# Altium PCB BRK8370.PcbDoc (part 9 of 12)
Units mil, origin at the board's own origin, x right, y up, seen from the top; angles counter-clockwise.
Board outline 8267.72 x 5708.66 mil, 6 copper layers (L1-TOP, L2-GND, L3-PWR, L4-PWR, L5-GND, L6-BOT), stack 68.606 mil thick; 319 components, 516 nets, 2008 pads, 1743 vias.
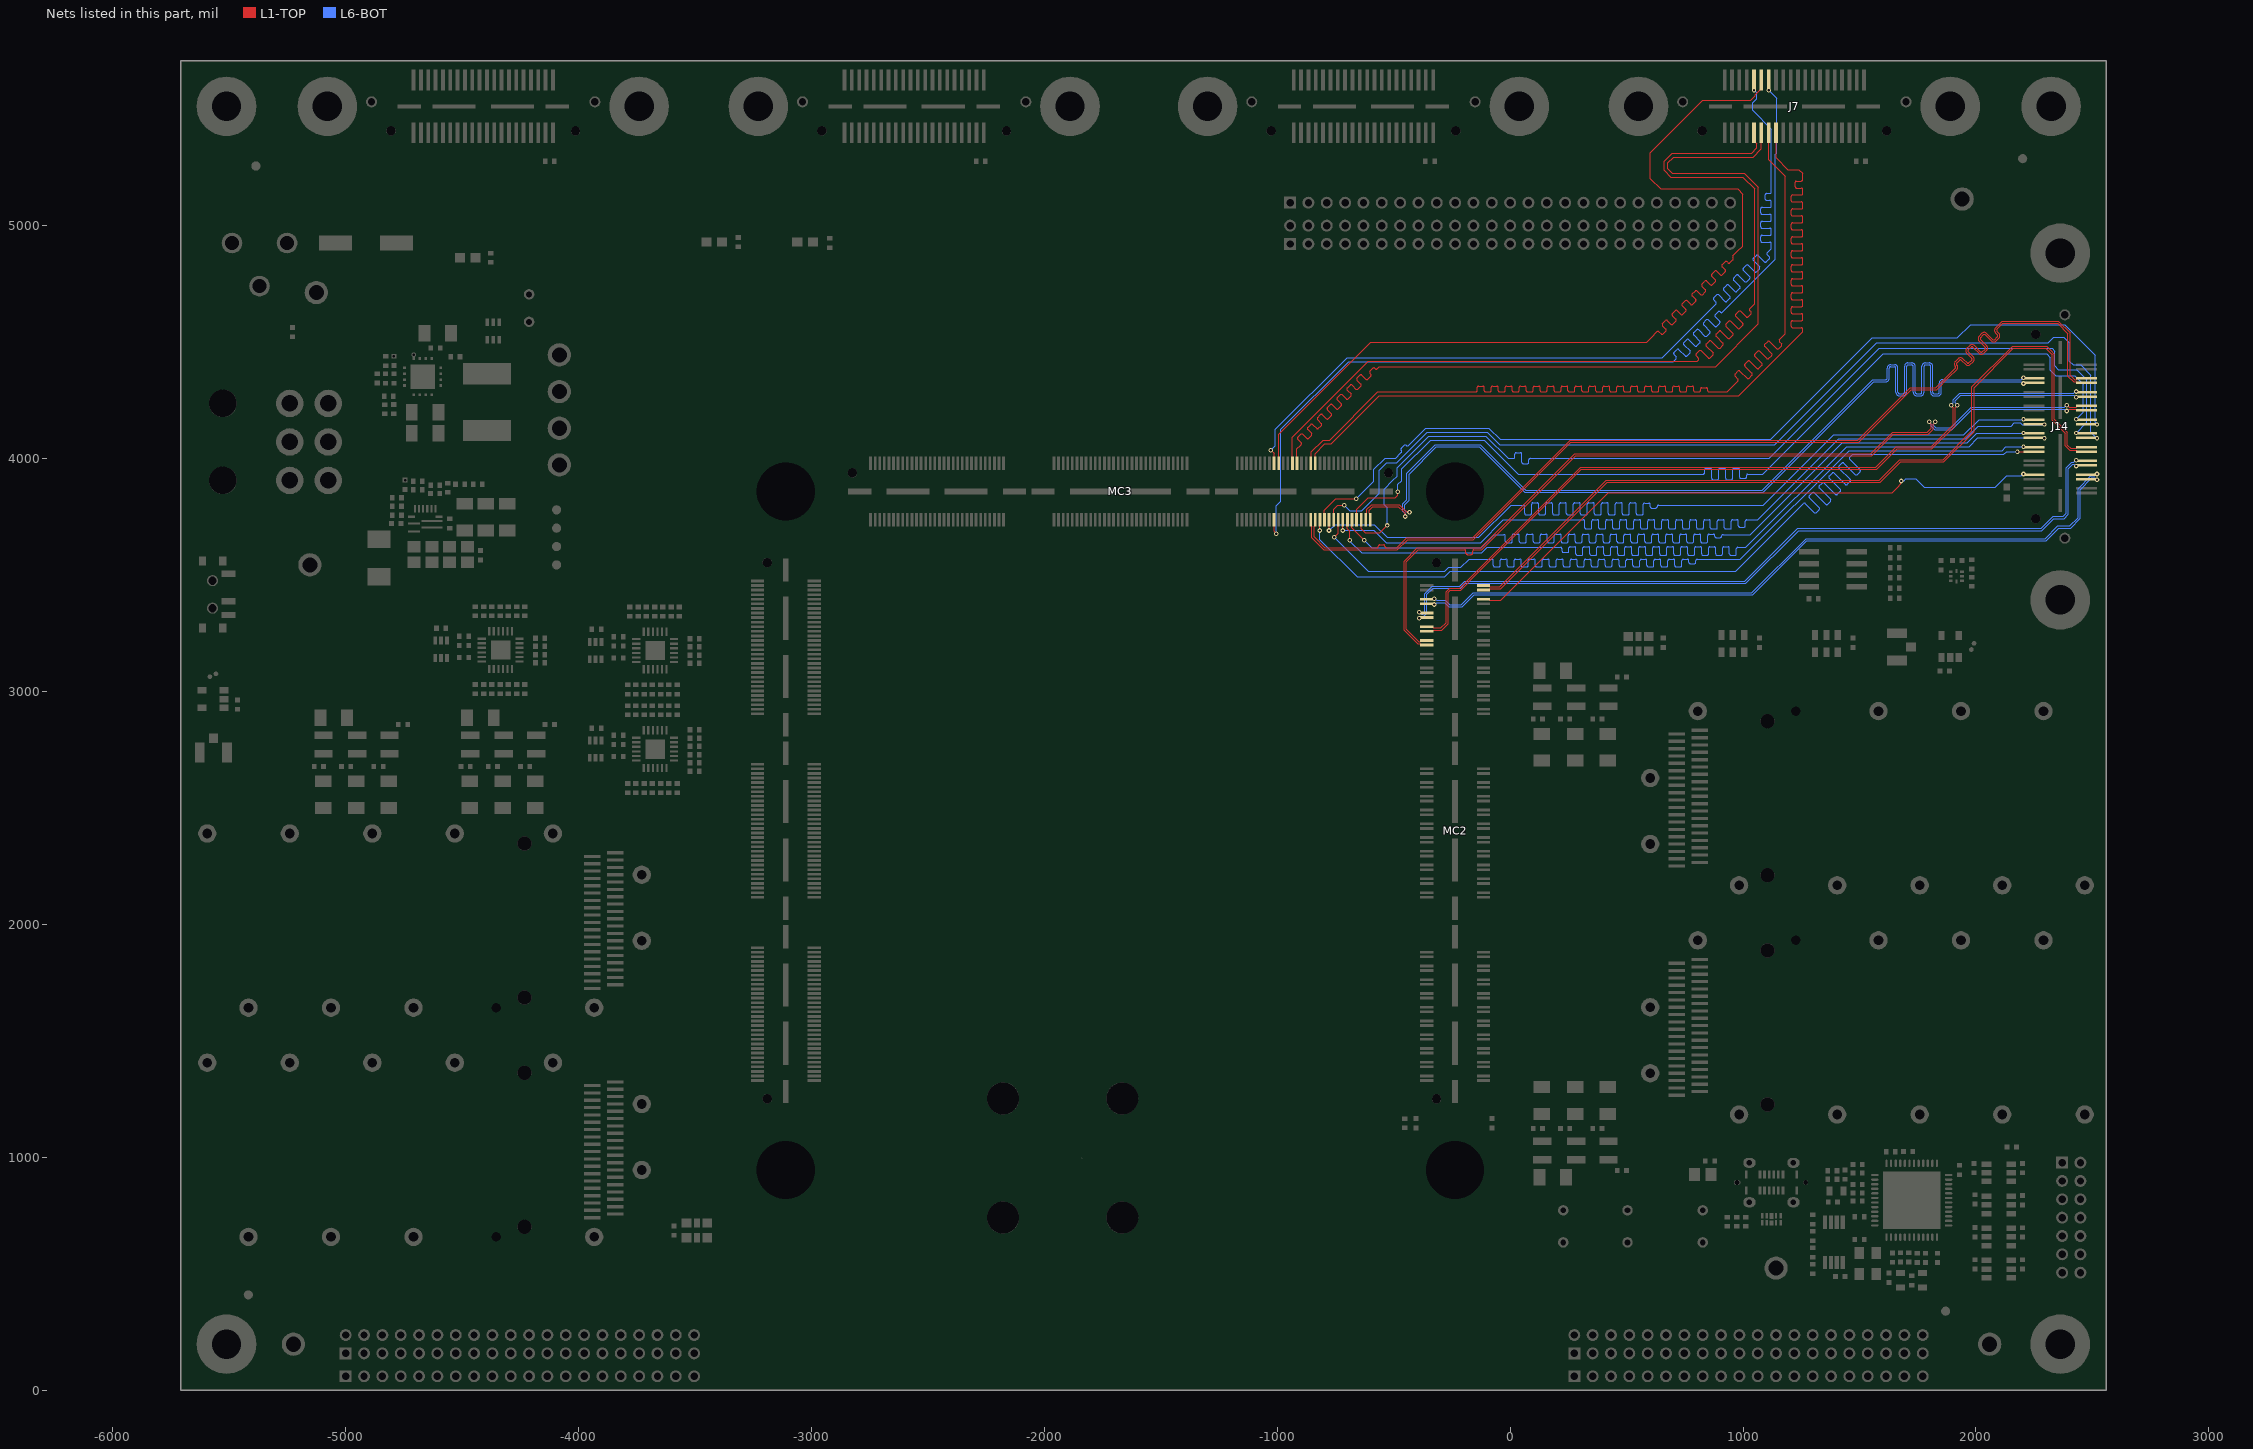
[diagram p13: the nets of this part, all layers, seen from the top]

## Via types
v1: diameter 20, hole 10, L1-TOP to L6-BOT, tented both sides, 957 vias
v2: diameter 18, hole 10, L1-TOP to L6-BOT, tented both sides, 786 vias

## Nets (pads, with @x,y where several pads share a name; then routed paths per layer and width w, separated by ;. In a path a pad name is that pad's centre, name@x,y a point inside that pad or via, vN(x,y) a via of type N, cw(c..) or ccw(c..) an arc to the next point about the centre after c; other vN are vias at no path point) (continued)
PORTD_S21: J7.26 MC3.155 | length 4242.4
  L1-TOP w4.96: MC3.155@-836.61,3979.92 -836.61,4020.87 -795.17,4062.31 -768.03,4062.31 -561.41,4268.93 981.53,4268.93 1255.91,4543.31 1255.91,4553.66 1255.91,4556.15 ccw(c1249.91,4556.15) 1249.91,4562.14 1212.45,4562.14 cw(c1212.45,4568.13) 1206.46,4568.13 1206.46,4586.11 cw(c1212.45,4586.11) 1212.45,4592.1 1250.97,4592.1 ccw(c1250.97,4598.09) 1256.96,4598.09 1256.96,4616.07 ccw(c1250.97,4616.07) 1250.97,4622.06 1212.45,4622.06 cw(c1212.45,4628.06) 1206.46,4628.06 1206.46,4646.03 cw(c1212.45,4646.03) 1212.45,4652.03 1250.97,4652.03 ccw(c1250.97,4658.02) 1256.96,4658.02 1256.96,4676 ccw(c1250.97,4676) 1250.97,4681.99 1212.45,4681.99 cw(c1212.45,4687.98) 1206.46,4687.98 1206.46,4705.96 cw(c1212.45,4705.96) 1212.45,4711.95 1250.97,4711.95 ccw(c1250.97,4717.95) 1256.96,4717.95 1256.96,4735.92 ccw(c1250.97,4735.92) 1250.97,4741.92 1212.45,4741.92 cw(c1212.45,4747.91) 1206.46,4747.91 1206.46,4765.89 cw(c1212.45,4765.89) 1212.45,4771.88 1250.97,4771.88 ccw(c1250.97,4777.87) 1256.96,4777.87 1256.96,4795.85 ccw(c1250.97,4795.85) 1250.97,4801.84 1212.45,4801.84 cw(c1212.45,4807.83) 1206.46,4807.83 1206.46,4825.81 cw(c1212.45,4825.81) 1212.45,4831.8 1250.97,4831.8 ccw(c1250.97,4837.8) 1256.96,4837.8 1256.96,4855.78 ccw(c1250.97,4855.78) 1250.97,4861.77 1212.45,4861.77 cw(c1212.45,4867.76) 1206.46,4867.76 1206.46,4885.74 cw(c1212.45,4885.74) 1212.45,4891.73 1250.97,4891.73 ccw(c1250.97,4897.72) 1256.96,4897.72 1256.96,4915.7 ccw(c1250.97,4915.7) 1250.97,4921.69 1212.45,4921.69 cw(c1212.45,4927.69) 1206.46,4927.69 1206.46,4945.66 cw(c1212.45,4945.66) 1212.45,4951.66 1250.97,4951.66 ccw(c1250.97,4957.65) 1256.96,4957.65 1256.96,4975.63 ccw(c1250.97,4975.63) 1250.97,4981.62 1212.45,4981.62 cw(c1212.45,4987.61) 1206.46,4987.61 1206.46,5005.59 cw(c1212.45,5005.59) 1212.45,5011.58 1250.97,5011.58 ccw(c1250.97,5017.58) 1256.96,5017.58 1256.96,5035.55 ccw(c1250.97,5035.55) 1250.97,5041.55 1212.45,5041.55 cw(c1212.45,5047.54) 1206.46,5047.54 1206.46,5065.52 cw(c1212.45,5065.52) 1212.45,5071.51 1250.97,5071.51 ccw(c1250.97,5077.5) 1256.96,5077.5 1256.96,5095.48 ccw(c1250.97,5095.48) 1250.97,5101.47 1212.45,5101.47 cw(c1212.45,5107.46) 1206.46,5107.46 1206.46,5125.44 cw(c1212.45,5125.44) 1212.45,5131.43 1250.97,5131.43 ccw(c1250.97,5137.43) 1256.96,5137.43 1256.96,5155.41 ccw(c1250.97,5155.41) 1250.97,5161.4 1229.4,5161.4 cw(c1229.4,5167.39) 1223.41,5167.39 1223.41,5185.37 cw(c1229.4,5185.37) 1229.4,5191.36 1249.91,5191.36 ccw(c1249.91,5197.35) 1255.91,5197.35 1255.91,5211.44 1255.91,5224.41 1240.16,5240.16 1192.91,5240.16 1141.77,5291.3 J7.26@1141.77,5399.01
PORTD_S22: J7.27 MC3.138 | length 4064.5
  L1-TOP w4.96: MC3.138@-1013.78,3736.61 -1013.78,3687.01 v1(-1003.94,3677.17)
  L6-BOT w4.96: v1(-1003.94,3677.17) -1003.94,3797.3 -984.63,3816.61 -984.63,4055.12 -984.63,4125.06 -693.27,4416.42 699.88,4416.42 710.63,4427.17 712.38,4428.92 ccw(c708.15,4433.16) 712.38,4437.4 703.18,4446.6 cw(c707.42,4450.84) 703.18,4455.07 715.89,4467.79 cw(c720.13,4463.55) 724.37,4467.79 751.25,4440.9 ccw(c755.49,4445.14) 759.72,4440.9 772.44,4453.62 ccw(c768.2,4457.85) 772.44,4462.09 745.56,4488.97 cw(c749.79,4493.21) 745.56,4497.45 758.27,4510.16 cw(c762.51,4505.92) 766.74,4510.16 793.62,4483.28 ccw(c797.86,4487.52) 802.1,4483.28 814.81,4495.99 ccw(c810.57,4500.23) 814.81,4504.47 787.93,4531.35 cw(c792.17,4535.58) 787.93,4539.82 800.64,4552.53 cw(c804.88,4548.3) 809.12,4552.53 836,4525.65 ccw(c840.24,4529.89) 844.47,4525.65 857.18,4538.36 ccw(c852.95,4542.6) 857.18,4546.84 830.3,4573.72 cw(c834.54,4577.96) 830.3,4582.2 843.02,4594.91 cw(c847.25,4590.67) 851.49,4594.91 878.37,4568.03 ccw(c882.61,4572.26) 886.85,4568.03 899.56,4580.74 ccw(c895.32,4584.98) 899.56,4589.21 880.34,4608.43 cw(c884.58,4612.67) 880.34,4616.91 893.05,4629.62 cw(c897.29,4625.38) 901.53,4629.62 903.07,4628.08 ccw(c907.31,4632.32) 911.54,4628.08 964.57,4681.1 1138.65,4855.18 1138.65,5305.88 1144.22,5311.45 1144.22,5547.2 v2(1110.17,5581.25)
PORTD_S23: J7.28 MC3.153 | length 4243.4
  L1-TOP w4.96: MC3.153@-856.3,3979.92 -853.58,3982.64 -853.58,4027.9 -802.2,4079.27 -775.06,4079.27 -568.44,4285.89 -149.61,4285.89 -147.12,4285.89 ccw(c-147.12,4291.89) -141.13,4291.89 -141.13,4304.9 cw(c-135.14,4304.9) -135.14,4310.89 -117.16,4310.89 cw(c-117.16,4304.9) -111.17,4304.9 -111.17,4291.89 ccw(c-105.18,4291.89) -105.18,4285.89 -87.2,4285.89 ccw(c-87.2,4291.89) -81.21,4291.89 -81.21,4304.9 cw(c-75.21,4304.9) -75.21,4310.89 -57.24,4310.89 cw(c-57.24,4304.9) -51.24,4304.9 -51.24,4291.89 ccw(c-45.25,4291.89) -45.25,4285.89 -27.27,4285.89 ccw(c-27.27,4291.89) -21.28,4291.89 -21.28,4304.9 cw(c-15.29,4304.9) -15.29,4310.89 2.69,4310.89 cw(c2.69,4304.9) 8.68,4304.9 8.68,4291.89 ccw(c14.68,4291.89) 14.68,4285.89 32.65,4285.89 ccw(c32.65,4291.89) 38.65,4291.89 38.65,4304.9 cw(c44.64,4304.9) 44.64,4310.89 62.62,4310.89 cw(c62.62,4304.9) 68.61,4304.9 68.61,4291.89 ccw(c74.6,4291.89) 74.6,4285.89 92.58,4285.89 ccw(c92.58,4291.89) 98.57,4291.89 98.57,4304.9 cw(c104.56,4304.9) 104.56,4310.89 122.54,4310.89 cw(c122.54,4304.9) 128.54,4304.9 128.54,4291.89 ccw(c134.53,4291.89) 134.53,4285.89 152.51,4285.89 ccw(c152.51,4291.89) 158.5,4291.89 158.5,4304.9 cw(c164.49,4304.9) 164.49,4310.89 182.47,4310.89 cw(c182.47,4304.9) 188.46,4304.9 188.46,4291.89 ccw(c194.45,4291.89) 194.45,4285.89 212.43,4285.89 ccw(c212.43,4291.89) 218.42,4291.89 218.42,4304.9 cw(c224.42,4304.9) 224.42,4310.89 242.39,4310.89 cw(c242.39,4304.9) 248.39,4304.9 248.39,4291.89 ccw(c254.38,4291.89) 254.38,4285.89 272.36,4285.89 ccw(c272.36,4291.89) 278.35,4291.89 278.35,4304.9 cw(c284.34,4304.9) 284.34,4310.89 302.32,4310.89 cw(c302.32,4304.9) 308.31,4304.9 308.31,4291.89 ccw(c314.31,4291.89) 314.31,4285.89 332.28,4285.89 ccw(c332.28,4291.89) 338.28,4291.89 338.28,4304.9 cw(c344.27,4304.9) 344.27,4310.89 362.25,4310.89 cw(c362.25,4304.9) 368.24,4304.9 368.24,4291.89 ccw(c374.23,4291.89) 374.23,4285.89 392.21,4285.89 ccw(c392.21,4291.89) 398.2,4291.89 398.2,4304.9 cw(c404.19,4304.9) 404.19,4310.89 422.17,4310.89 cw(c422.17,4304.9) 428.17,4304.9 428.17,4291.89 ccw(c434.16,4291.89) 434.16,4285.89 452.14,4285.89 ccw(c452.14,4291.89) 458.13,4291.89 458.13,4304.9 cw(c464.12,4304.9) 464.12,4310.89 482.1,4310.89 cw(c482.1,4304.9) 488.09,4304.9 488.09,4291.89 ccw(c494.08,4291.89) 494.08,4285.89 512.06,4285.89 ccw(c512.06,4291.89) 518.05,4291.89 518.05,4304.9 cw(c524.05,4304.9) 524.05,4310.89 542.02,4310.89 cw(c542.02,4304.9) 548.02,4304.9 548.02,4291.89 ccw(c554.01,4291.89) 554.01,4285.89 571.99,4285.89 ccw(c571.99,4291.89) 577.98,4291.89 577.98,4304.9 cw(c583.97,4304.9) 583.97,4310.89 601.95,4310.89 cw(c601.95,4304.9) 607.94,4304.9 607.94,4291.89 ccw(c613.94,4291.89) 613.94,4285.89 631.91,4285.89 ccw(c631.91,4291.89) 637.91,4291.89 637.91,4304.9 cw(c643.9,4304.9) 643.9,4310.89 661.88,4310.89 cw(c661.88,4304.9) 667.87,4304.9 667.87,4291.89 ccw(c673.86,4291.89) 673.86,4285.89 691.84,4285.89 ccw(c691.84,4291.89) 697.83,4291.89 697.83,4304.9 cw(c703.82,4304.9) 703.82,4310.89 721.8,4310.89 cw(c721.8,4304.9) 727.8,4304.9 727.8,4291.89 ccw(c733.79,4291.89) 733.79,4285.89 751.77,4285.89 ccw(c751.77,4291.89) 757.76,4291.89 757.76,4304.9 cw(c763.75,4304.9) 763.75,4310.89 781.73,4310.89 cw(c781.73,4304.9) 787.72,4304.9 787.72,4291.89 ccw(c793.71,4291.89) 793.71,4285.89 811.69,4285.89 ccw(c811.69,4291.89) 817.68,4291.89 817.68,4298.63 cw(c823.68,4298.63) 823.68,4304.63 841.65,4304.63 cw(c841.65,4298.63) 847.65,4298.63 847.65,4291.89 ccw(c853.64,4291.89) 853.64,4285.89 893.7,4285.89 931.56,4285.89 976.67,4331 978.42,4332.75 ccw(c974.19,4336.99) 978.42,4341.23 965.66,4353.99 cw(c969.9,4358.23) 965.66,4362.47 978.37,4375.18 cw(c982.61,4370.94) 986.85,4375.18 1017.29,4344.74 ccw(c1021.53,4348.98) 1025.76,4344.74 1038.48,4357.45 ccw(c1034.24,4361.69) 1038.48,4365.93 1008.03,4396.37 cw(c1012.27,4400.6) 1008.03,4404.84 1020.75,4417.55 cw(c1024.98,4413.32) 1029.22,4417.55 1059.66,4387.11 ccw(c1063.9,4391.35) 1068.14,4387.11 1080.85,4399.82 ccw(c1076.61,4404.06) 1080.85,4408.3 1050.41,4438.74 cw(c1054.64,4442.98) 1050.41,4447.22 1063.12,4459.93 cw(c1067.36,4455.69) 1071.59,4459.93 1102.04,4429.49 ccw(c1106.27,4433.72) 1110.51,4429.49 1123.22,4442.2 ccw(c1118.99,4446.44) 1123.22,4450.67 1092.78,4481.12 cw(c1097.02,4485.35) 1092.78,4489.59 1105.49,4502.3 cw(c1109.73,4498.07) 1113.97,4502.3 1144.41,4471.86 ccw(c1148.65,4476.1) 1152.89,4471.86 1165.6,4484.57 ccw(c1161.36,4488.81) 1165.6,4493.05 1156.39,4502.25 cw(c1160.63,4506.49) 1156.39,4510.73 1177.27,4531.6 1181,4535.33 1181,5212.7 1110.27,5283.43 J7.28@1110.27,5399.01
PORTD_S24: J7.29 MC3.139 | length 4245
  L1-TOP w4.96: MC3.139@-994.09,3979.92 -994.09,4104.33 -598.43,4500 586.61,4500 607.44,4520.82 630.38,4543.77 cw(c634.62,4539.53) 638.85,4543.77 648.06,4534.56 ccw(c652.3,4538.8) 656.53,4534.56 669.24,4547.27 ccw(c665.01,4551.51) 669.24,4555.75 654.14,4570.86 cw(c658.37,4575.1) 654.13,4579.33 666.85,4592.05 cw(c671.08,4587.81) 675.32,4592.05 690.43,4576.94 ccw(c694.67,4581.17) 698.91,4576.94 711.62,4589.65 ccw(c707.38,4593.89) 711.62,4598.12 696.51,4613.23 cw(c700.75,4617.47) 696.51,4621.71 709.22,4634.42 cw(c713.46,4630.18) 717.7,4634.42 732.81,4619.31 ccw(c737.04,4623.55) 741.28,4619.31 753.99,4632.02 ccw(c749.76,4636.26) 753.99,4640.5 738.88,4655.61 cw(c743.12,4659.85) 738.88,4664.08 751.6,4676.79 cw(c755.83,4672.56) 760.07,4676.79 775.18,4661.68 ccw(c779.42,4665.92) 783.65,4661.68 796.37,4674.4 ccw(c792.13,4678.63) 796.37,4682.87 781.26,4697.98 cw(c785.49,4702.22) 781.26,4706.46 793.97,4719.17 cw(c798.21,4714.93) 802.44,4719.17 817.55,4704.06 ccw(c821.79,4708.3) 826.03,4704.06 838.74,4716.77 ccw(c834.5,4721.01) 838.74,4725.25 823.63,4740.36 cw(c827.87,4744.59) 823.63,4748.83 836.34,4761.54 cw(c840.58,4757.31) 844.82,4761.54 859.93,4746.43 ccw(c864.17,4750.67) 868.4,4746.43 881.12,4759.15 ccw(c876.88,4763.38) 881.12,4767.62 866.01,4782.73 cw(c870.24,4786.97) 866.01,4791.2 878.72,4803.92 cw(c882.95,4799.68) 887.19,4803.92 902.24,4788.87 ccw(c906.47,4793.11) 910.71,4788.87 923.42,4801.59 ccw(c919.19,4805.82) 923.42,4810.06 910.05,4823.44 cw(c914.29,4827.67) 910.05,4831.91 922.76,4844.62 cw(c927,4840.38) 931.24,4844.62 935.47,4840.38 ccw(c939.71,4844.62) 943.95,4840.38 956.66,4853.1 ccw(c952.42,4857.33) 956.66,4861.57 cw(c960.9,4865.81) 956.66,4870.05 978.35,4891.73 998.56,4911.94 998.56,5135.3 976.38,5157.48 645.67,5157.48 601.53,5201.62 601.53,5313.7 826.03,5538.2 1032.91,5538.2 1053.08,5558.37 1053.08,5562.17 1078.77,5587.86 J7.29@1078.77,5624.61
PORTD_S25: J7.30 MC3.147 | length 4242.4
  L1-TOP w4.96: MC3.147@-915.35,3979.92 -915.35,4041.34 -899.16,4057.53 -897.41,4059.29 ccw(c-901.64,4063.52) -897.41,4067.76 -911.82,4082.17 cw(c-907.58,4086.41) -911.82,4090.65 -899.11,4103.36 cw(c-894.87,4099.12) -890.63,4103.36 -873.73,4086.46 ccw(c-869.5,4090.7) -865.26,4086.46 -852.55,4099.17 ccw(c-856.78,4103.41) -852.55,4107.65 -869.45,4124.55 cw(c-865.21,4128.79) -869.45,4133.02 -856.73,4145.73 cw(c-852.5,4141.5) -848.26,4145.73 -831.36,4128.84 ccw(c-827.12,4133.07) -822.88,4128.84 -810.17,4141.55 ccw(c-814.41,4145.79) -810.17,4150.02 -827.07,4166.92 cw(c-822.83,4171.16) -827.07,4175.4 -814.36,4188.11 cw(c-810.12,4183.87) -805.88,4188.11 -788.99,4171.21 ccw(c-784.75,4175.45) -780.51,4171.21 -767.8,4183.92 ccw(c-772.04,4188.16) -767.8,4192.4 -784.7,4209.3 cw(c-780.46,4213.53) -784.7,4217.77 -771.98,4230.48 cw(c-767.75,4226.25) -763.51,4230.48 -746.61,4213.58 ccw(c-742.37,4217.82) -738.14,4213.58 -725.42,4226.3 ccw(c-729.66,4230.53) -725.42,4234.77 -742.32,4251.67 cw(c-738.09,4255.91) -742.32,4260.14 -729.61,4272.86 cw(c-725.37,4268.62) -721.14,4272.86 -704.24,4255.96 ccw(c-700,4260.2) -695.76,4255.96 -683.05,4268.67 ccw(c-687.29,4272.91) -683.05,4277.15 -699.95,4294.04 cw(c-695.71,4298.28) -699.95,4302.52 -687.24,4315.23 cw(c-683,4310.99) -678.76,4315.23 -661.86,4298.33 ccw(c-657.63,4302.57) -653.39,4298.33 -640.68,4311.04 ccw(c-644.91,4315.28) -640.68,4319.52 -657.57,4336.42 cw(c-653.34,4340.66) -657.57,4344.89 ; -657.57,4344.89 -644.86,4357.61 cw(c-640.63,4353.37) -636.39,4357.61 -619.49,4340.71 ccw(c-615.25,4344.94) -611.01,4340.71 -598.3,4353.42 ccw(c-602.54,4357.66) -598.3,4361.89 -602.04,4365.63 cw(c-597.8,4369.87) -602.04,4374.1 -589.32,4386.82 cw(c-585.09,4382.58) -580.85,4386.82 -579.6,4385.57 ccw(c-575.36,4389.8) -571.13,4385.57 -562.7,4393.99 -559.59,4393.99 882.18,4393.99 1066.41,4578.22 1066.41,5164.73 1005.81,5225.33 696.29,5225.33 677.67,5243.96 677.67,5269.41 702.32,5294.06 1043.76,5294.06 1078.77,5329.07 J7.30@1078.77,5399.01
PORTD_S26: J7.31 MC3.137 | length 4064.5
  L1-TOP w4.96: v1(-1027.56,4035.43) -1013.78,4021.65 MC3.137@-1013.78,3979.92
  L6-BOT w4.96: v1(-1027.56,4035.43) -1007.87,4055.12 -1007.87,4125.8 -700.29,4433.38 653.85,4433.38 881.89,4661.42 883.64,4663.17 ccw(c879.41,4667.41) 883.64,4671.65 874.44,4680.85 cw(c878.68,4685.09) 874.44,4689.32 887.15,4702.04 cw(c891.39,4697.8) 895.63,4702.04 922.51,4675.16 ccw(c926.75,4679.39) 930.98,4675.16 943.7,4687.87 ccw(c939.46,4692.11) 943.7,4696.34 916.82,4723.22 cw(c921.05,4727.46) 916.82,4731.7 929.53,4744.41 cw(c933.77,4740.17) 938,4744.41 964.88,4717.53 ccw(c969.12,4721.77) 973.36,4717.53 986.07,4730.24 ccw(c981.83,4734.48) 986.07,4738.72 959.19,4765.6 cw(c963.43,4769.84) 959.19,4774.07 971.9,4786.79 cw(c976.14,4782.55) 980.38,4786.79 1007.26,4759.9 ccw(c1011.5,4764.14) 1015.73,4759.9 1028.44,4772.62 ccw(c1024.21,4776.85) 1028.44,4781.09 1001.56,4807.97 cw(c1005.8,4812.21) 1001.56,4816.45 1014.28,4829.16 cw(c1018.51,4824.92) 1022.75,4829.16 ; 1022.75,4829.16 1049.63,4802.28 ccw(c1053.87,4806.52) 1058.11,4802.28 1070.82,4814.99 ccw(c1066.58,4819.23) 1070.82,4823.47 1043.94,4850.35 cw(c1048.18,4854.58) 1043.94,4858.82 1056.65,4871.53 cw(c1060.89,4867.3) 1065.13,4871.53 1092.01,4844.65 ccw(c1096.24,4848.89) 1100.48,4844.65 1113.19,4857.36 ccw(c1108.96,4861.6) 1113.19,4865.84 1103.99,4875.04 cw(c1108.23,4879.28) 1103.99,4883.52 1112.2,4891.73 1121.68,4901.21 1121.68,4919.8 1121.68,4922.29 ccw(c1115.69,4922.29) 1115.69,4928.28 1082,4928.28 cw(c1082,4934.27) 1076.01,4934.27 1076.01,4952.25 cw(c1082,4952.25) 1082,4958.24 1115.69,4958.24 ccw(c1115.69,4964.24) 1121.68,4964.24 1121.68,4982.21 ccw(c1115.69,4982.21) 1115.69,4988.21 1082,4988.21 cw(c1082,4994.2) 1076.01,4994.2 1076.01,5012.18 cw(c1082,5012.18) 1082,5018.17 1115.69,5018.17 ccw(c1115.69,5024.16) 1121.68,5024.16 1121.68,5042.14 ccw(c1115.69,5042.14) 1115.69,5048.13 1082,5048.13 cw(c1082,5054.12) 1076.01,5054.12 1076.01,5072.1 cw(c1082,5072.1) 1082,5078.09 1115.69,5078.09 ccw(c1115.69,5084.09) 1121.68,5084.09 1121.68,5102.06 ccw(c1115.69,5102.06) 1115.69,5108.06 1101.95,5108.06 cw(c1101.95,5114.05) 1095.96,5114.05 1095.96,5132.03 cw(c1101.95,5132.03) 1101.95,5138.02 1115.69,5138.02 ccw(c1115.69,5144.01) 1121.68,5144.01 1121.68,5188.98 1121.68,5307.93 1122.05,5308.29 1122.05,5413.39 1040.92,5494.51 1040.92,5526.75 1059.06,5544.88 1059.06,5569.37 v2(1047.17,5581.25)
PORTD_S27: J7.32 MC3.145 | length 4245
  L1-TOP w4.96: MC3.145@-935.04,3979.92 -935.04,4091.42 -609.13,4417.32 803.15,4417.32 806.86,4421.03 808.61,4422.79 ccw(c804.37,4427.02) 808.61,4431.26 799.41,4440.46 cw(c803.65,4444.7) 799.41,4448.94 812.12,4461.65 cw(c816.36,4457.41) 820.6,4461.65 850.3,4431.94 ccw(c854.54,4436.18) 858.78,4431.94 871.49,4444.66 ccw(c867.25,4448.89) 871.49,4453.13 841.78,4482.84 cw(c846.02,4487.07) 841.78,4491.31 854.5,4504.02 cw(c858.73,4499.79) 862.97,4504.02 892.68,4474.32 ccw(c896.91,4478.56) 901.15,4474.32 913.86,4487.03 ccw(c909.63,4491.27) 913.86,4495.5 884.16,4525.21 cw(c888.4,4529.45) 884.16,4533.69 896.87,4546.4 cw(c901.11,4542.16) 905.34,4546.4 935.05,4516.69 ccw(c939.29,4520.93) 943.53,4516.69 956.24,4529.4 ccw(c952,4533.64) 956.24,4537.88 926.53,4567.59 cw(c930.77,4571.82) 926.53,4576.06 939.24,4588.77 cw(c943.48,4584.53) 947.72,4588.77 977.43,4559.07 ccw(c981.66,4563.3) 985.9,4559.07 998.61,4571.78 ccw(c994.37,4576.02) 998.61,4580.25 968.91,4609.96 cw(c973.14,4614.2) 968.91,4618.43 981.62,4631.15 cw(c985.86,4626.91) 990.09,4631.15 1013.09,4608.15 ccw(c1017.33,4612.39) 1021.56,4608.15 1034.28,4620.86 ccw(c1030.04,4625.1) 1034.28,4629.34 1028.96,4634.66 cw(c1033.19,4638.89) 1028.96,4643.13 1047.91,4662.08 1049.45,4663.62 1049.45,5157.71 998.78,5208.37 689.27,5208.37 660.71,5236.93 660.71,5276.43 695.3,5311.02 1036.74,5311.02 1059.06,5333.34 1059.06,5350.48 1047.27,5362.26 J7.32@1047.27,5399.01
PORTE_C2P_CLK_N: J14.36 MC3.180 | length 4121.2
  L1-TOP w3.3: MC3.180@-600.39,3736.61 -600.39,3759.25 -605.74,3764.59 -605.74,3777.53 -590.8,3792.46 -479.85,3792.46 -462.09,3774.7 -451.36,3763.97 -451.36,3752.66 v1(-449.74,3751.04)
  L6-BOT w3.3: v1(-449.74,3751.04) -451.36,3752.66 -451.36,3763.97 -461.15,3773.76 -461.15,3805.88 -443.2,3823.83 -443.2,3936.28 -321.13,4058.34 -127.96,4058.34 67.05,3863.33 1082.49,3863.33 1557.86,4338.7 1565.32,4338.7 1613.33,4338.7 ccw(c1613.33,4344.36) 1618.99,4344.36 1618.99,4388.35 cw(c1633.65,4388.35) 1633.65,4403.01 1650.63,4403.01 cw(c1650.63,4388.35) 1665.29,4388.35 1665.29,4284.23 ccw(c1670.95,4284.23) 1670.95,4278.57 1687.93,4278.57 ccw(c1687.93,4284.23) 1693.59,4284.23 1693.59,4395.81 cw(c1708.25,4395.81) 1708.25,4410.47 1725.23,4410.47 cw(c1725.23,4395.81) 1739.89,4395.81 1739.89,4284.23 ccw(c1745.55,4284.23) 1745.55,4278.57 1762.53,4278.57 ccw(c1762.53,4284.23) 1768.19,4284.23 1768.19,4395.81 cw(c1782.85,4395.81) 1782.85,4410.47 1799.83,4410.47 cw(c1799.83,4395.81) 1814.49,4395.81 1814.49,4284.23 ccw(c1820.15,4284.23) 1820.15,4278.57 1837.13,4278.57 ccw(c1837.13,4284.23) 1842.79,4284.23 1842.79,4324.04 cw(c1857.45,4324.04) 1857.45,4338.7 1863.6,4338.7 2194.24,4338.7 2202.24,4346.7 v1(2204.53,4346.7)
PORTE_C2P_CLK_P: J14.34 MC3.178 | length 4121.2
  L1-TOP w3.3: MC3.178@-620.08,3736.61 -620.08,3759.25 -614.74,3764.59 -614.74,3781.25 -594.53,3801.46 -476.12,3801.46 -458.36,3783.7 -444.99,3770.34 -433.68,3770.34 v1(-432.07,3768.72)
  L6-BOT w3.3: v1(-432.07,3768.72) -433.68,3770.34 -444.99,3770.34 -452.15,3777.49 -452.15,3802.15 -434.2,3820.1 -434.2,3932.55 -317.4,4049.34 -131.69,4049.34 63.32,3854.33 1086.22,3854.33 1561.59,4329.7 1565.32,4329.7 1613.33,4329.7 ccw(c1613.33,4344.36) 1627.99,4344.36 1627.99,4388.35 cw(c1633.65,4388.35) 1633.65,4394.01 1650.63,4394.01 cw(c1650.63,4388.35) 1656.29,4388.35 1656.29,4284.23 ccw(c1670.95,4284.23) 1670.95,4269.57 1687.93,4269.57 ccw(c1687.93,4284.23) 1702.59,4284.23 1702.59,4395.81 cw(c1708.25,4395.81) 1708.25,4401.47 1725.23,4401.47 cw(c1725.23,4395.81) 1730.89,4395.81 1730.89,4284.23 ccw(c1745.55,4284.23) 1745.55,4269.57 1762.53,4269.57 ccw(c1762.53,4284.23) 1777.19,4284.23 1777.19,4395.81 cw(c1782.85,4395.81) 1782.85,4401.47 1799.83,4401.47 cw(c1799.83,4395.81) 1805.49,4395.81 1805.49,4284.23 ccw(c1820.15,4284.23) 1820.15,4269.57 1837.13,4269.57 ccw(c1837.13,4284.23) 1851.79,4284.23 1851.79,4324.04 cw(c1857.45,4324.04) 1857.45,4329.7 1863.6,4329.7 2194.24,4329.7 2202.24,4321.7 v1(2204.53,4321.7)
PORTE_P2C_CLK_N: J14.35 MC3.156 | length 4302.4
  L1-TOP w3.3: MC3.156@-836.61,3736.61 -836.61,3713.98 -841.96,3708.63 -841.96,3663.2 -795.74,3616.99 -590.55,3616.99 -571.31,3616.99 ccw(c-571.31,3622.65) -565.65,3622.65 -565.65,3623.67 cw(c-559.99,3623.67) -559.99,3629.33 -543.01,3629.33 cw(c-543.01,3623.67) -537.35,3623.67 -537.35,3622.65 ccw(c-531.69,3622.65) -531.69,3616.99 -501.74,3616.99 -487.72,3616.99 -444.42,3660.29 -161.11,3660.29 257.33,4078.74 1492.13,4078.74 1717.66,4304.28 1827.9,4304.28 1879.92,4356.3 1911.2,4387.58 ccw(c1907.2,4391.58) 1911.19,4395.6 cw(c1921.57,4405.95) 1911.2,4416.32 1923.25,4428.36 cw(c1933.58,4417.96) 1943.94,4428.33 1962.05,4410.22 ccw(c1966.05,4414.22) 1970.06,4410.22 1982.06,4422.22 ccw(c1978.06,4426.22) 1982.06,4430.23 1960.67,4451.62 cw(c1971.01,4462.01) 1960.64,4472.38 1972.69,4484.42 cw(c1983.02,4474.02) 1991.87,4485.7 1992.06,4485.7 2019.68,4458.09 ccw(c2023.67,4462.1) 2027.68,4458.1 2039.68,4470.1 ccw(c2035.68,4474.1) 2039.67,4478.12 2013.42,4504.37 cw(c2023.76,4514.76) 2013.39,4525.13 2025.44,4537.17 cw(c2035.77,4526.77) 2044.62,4538.45 2044.81,4538.45 2072.43,4510.84 ccw(c2076.42,4514.85) 2080.43,4510.85 2092.43,4522.85 ccw(c2088.43,4526.85) 2092.42,4530.87 2083.82,4539.47 cw(c2094.19,4549.83) 2083.82,4560.2 2088.17,4564.55 2112.49,4588.87 2354.59,4588.87 2404.39,4539.07 2404.39,4357.76 2423.45,4338.7 2430.68,4338.7 2436.02,4344.04 J14.35@2475.2,4344.04
PORTE_P2C_CLK_P: J14.33 MC3.154 | length 4302.4
  L1-TOP w3.3: MC3.154@-856.3,3736.61 -856.3,3713.98 -850.96,3708.63 -850.96,3659.47 -799.47,3607.99 -484,3607.99 -440.69,3651.29 -157.39,3651.29 261.06,4069.74 1495.85,4069.74 1721.39,4295.28 1831.63,4295.28 1886.29,4349.94 1917.57,4381.22 ccw(c1907.2,4391.58) 1918.89,4400.44 1918.88,4400.63 1917.58,4401.93 ; 1917.57,4401.95 cw(c1921.57,4405.95) 1917.57,4409.95 1929.57,4421.96 cw(c1933.58,4417.96) 1937.58,4421.96 1955.69,4403.85 ccw(c1966.05,4414.22) 1976.42,4403.85 1988.46,4415.89 ccw(c1978.06,4426.22) 1988.43,4436.59 1973.54,4451.47 1967,4458.01 cw(c1971.01,4462.01) 1967.01,4466.01 1979.01,4478.02 cw(c1983.02,4474.02) 1987.03,4478.01 ; 1987.05,4477.99 2013.28,4451.76 ccw(c2023.67,4462.1) 2034.04,4451.73 2046.08,4463.77 ccw(c2035.68,4474.1) 2047.36,4482.96 2047.36,4483.15 2019.75,4510.76 cw(c2023.76,4514.76) 2019.76,4518.76 2031.76,4530.77 cw(c2035.77,4526.77) 2039.78,4530.76 ; 2039.8,4530.74 2066.03,4504.51 ccw(c2076.42,4514.85) 2086.79,4504.48 2098.83,4516.52 ccw(c2088.43,4526.85) 2100.11,4535.71 2100.11,4535.9 2090.19,4545.83 cw(c2094.19,4549.83) 2090.19,4553.84 2094.53,4558.18 2116.22,4579.87 2350.86,4579.87 2395.39,4535.34 2395.39,4354.03 2419.72,4329.7 2430.68,4329.7 2436.02,4324.36 J14.33@2475.2,4324.36
PORTE_REFCLK_N: J14.15 MC2.120 | length 3511.2
  L1-TOP w3.3: MC2.120@-114.57,3454.72 -91.93,3454.72 -86.59,3449.38 -61.42,3449.38 -45.09,3449.38 412.73,3907.2 1585.96,3907.2 1673.69,3994.94 1858.73,3994.94 1982.98,4119.19 1982.98,4308.33 2157.22,4482.57 2303.41,4482.57 2321.69,4464.28 2337.4,4448.57 2337.4,4167.63 2393.01,4112.03 2393.01,4057.71 2407.29,4043.43 2418.64,4043.43 2430.68,4043.43 2436.02,4048.77 J14.15@2475.2,4048.77
PORTE_REFCLK_P: J14.13 MC2.118 | length 3511.2
  L1-TOP w3.3: MC2.118@-114.57,3435.04 -91.93,3435.04 -86.59,3440.38 -61.42,3440.38 -41.36,3440.38 416.46,3898.2 1589.69,3898.2 1677.42,3985.94 1862.46,3985.94 1991.98,4115.46 1991.98,4304.6 2160.95,4473.57 2299.68,4473.57 2308.96,4464.28 2328.4,4444.84 2328.4,4163.91 2384.01,4108.3 2384.01,4053.98 2403.57,4034.43 2422.36,4034.43 2430.68,4034.43 2436.02,4029.08 J14.13@2475.2,4029.08
PORTE_RX0_N: J14.7 MC2.115 | length 3161.8
  L6-BOT w3.3: v1(-325.98,3398.33) -323.7,3398.33 -315.7,3390.33 -277.58,3390.33 -259.32,3372.06 -209.4,3372.06 -157.39,3424.07 -61.42,3424.07 1038.19,3424.07 1270.48,3656.36 2297.93,3656.36 2351.85,3710.27 2402.47,3710.27 2438.69,3746.5 2438.69,3794.99 2438.69,3870.34 2493.67,3925.32 2509.6,3925.32 2517.6,3933.32 v1(2519.88,3933.32)
PORTE_RX0_P: J14.5 MC2.113 | length 3161.8
  L6-BOT w3.3: v1(-325.98,3373.33) -323.7,3373.33 -315.7,3381.33 -281.31,3381.33 -263.04,3363.06 -205.68,3363.06 -153.67,3415.07 -61.42,3415.07 1041.92,3415.07 1274.2,3647.36 2301.66,3647.36 2355.58,3701.27 2406.2,3701.27 2447.69,3742.77 2447.69,3794.99 2447.69,3866.61 2497.4,3916.32 2509.6,3916.32 2517.6,3908.32 v1(2519.88,3908.32)
PORTE_RX1_N: J14.11 MC2.111 | length 3259.3
  L6-BOT w3.3: v1(-389.76,3339.27) -387.48,3339.27 -379.48,3331.27 -374.22,3331.27 -366,3339.49 -366,3419.81 -334.18,3451.63 -216.41,3451.63 -195.62,3472.43 -61.42,3472.43 1007.81,3472.43 1235.04,3699.66 2279.99,3699.66 2331.26,3750.92 2374.56,3750.92 2387.51,3763.87 2387.51,3794.99 2387.51,3959.96 2411.92,3984.37 2420.23,3984.37 2428.23,3992.37 v1(2430.51,3992.37)
PORTE_RX1_P: J14.9 MC2.109 | length 3259.3
  L6-BOT w3.3: v1(-389.76,3314.27) -387.48,3314.27 -379.48,3322.27 -370.49,3322.27 -357,3335.76 -357,3416.09 -330.45,3442.63 -212.68,3442.63 -191.89,3463.43 -61.42,3463.43 1011.54,3463.43 1238.77,3690.66 2283.72,3690.66 2334.98,3741.92 2378.29,3741.92 2396.51,3760.15 2396.51,3794.99 2396.51,3956.23 2415.65,3975.37 2420.23,3975.37 2428.23,3967.37 v1(2430.51,3967.37)
PORTE_RX2_N: J14.31 MC2.107 | length 3358.7
  L1-TOP w3.3: MC2.107@-357.87,3277.56 -335.24,3277.56 -329.89,3272.22 -297.06,3272.22 -274.47,3294.81 -274.47,3428.83 -260.1,3443.2 -216.63,3443.2 -157.27,3502.56 302.49,3962.32 1570.21,3962.32 1657.95,4050.06 1807.55,4050.06 1902.7,4145.2 1902.7,4218.06 1894.7,4226.06 v1(1894.7,4228.35)
  L6-BOT w3.3: v1(1894.7,4228.35) 1894.7,4230.63 1902.7,4238.63 1902.7,4251.66 1930.68,4279.65 2184.92,4279.65 2420.23,4279.65 2428.23,4287.65 v1(2430.51,4287.65)
PORTE_RX2_P: J14.29 MC2.105 | length 3358.7
  L1-TOP w3.3: MC2.105@-357.87,3257.87 -335.24,3257.87 -329.89,3263.22 -293.33,3263.22 -265.47,3291.08 -265.47,3425.1 -256.37,3434.2 -212.9,3434.2 -144.54,3502.56 306.22,3953.32 1573.94,3953.32 1661.67,4041.06 1811.28,4041.06 1911.7,4141.48 1911.7,4218.06 1919.7,4226.06 v1(1919.7,4228.35)
  L6-BOT w3.3: v1(1919.7,4228.35) 1919.7,4230.63 1911.7,4238.63 1911.7,4247.94 1934.41,4270.65 2184.92,4270.65 2420.23,4270.65 2428.23,4262.65 v1(2430.51,4262.65)
PORTE_RX3_N: J14.27 MC2.103 | length 3692.3
  L1-TOP w3.3: MC2.103@-357.87,3218.5 -380.51,3218.5 -385.85,3213.16 -393.48,3213.16 -446.01,3265.68 -446.01,3436.24 -446.01,3456.69 -446.01,3544.3 -446.01,3555.75 -394.33,3607.42 -225.18,3607.42 -195.23,3607.42 cw(c-195.23,3601.76) -189.57,3601.76 -189.57,3593.31 ccw(c-183.91,3593.31) -183.91,3587.65 -166.93,3587.65 ccw(c-166.93,3593.31) -161.27,3593.31 -161.27,3601.76 cw(c-155.61,3601.76) -155.61,3607.42 -133.86,3607.42 -122.35,3607.42 280.91,4010.68 1552.56,4010.68 1645.93,4104.05 1795.53,4104.05 1817.21,4125.73 1817.21,4147.2 1825.21,4155.2 v1(1825.21,4157.48) ; v1(2389.76,4228.59) 2392.05,4228.59 2400.05,4220.59 2430.68,4220.59 2436.02,4225.93 J14.27@2475.2,4225.93
  L6-BOT w3.3: v1(1825.21,4157.48) 1825.21,4155.2 1817.21,4147.2 1817.21,4141.93 1826.51,4132.63 1891.96,4132.63 1979.92,4220.59 2379.48,4220.59 2387.48,4228.59 v1(2389.76,4228.59)
PORTE_RX3_P: J14.25 MC2.101 | length 3692.3
  L1-TOP w3.3: MC2.101@-357.87,3198.82 -380.51,3198.82 -385.85,3204.16 -397.21,3204.16 -433.07,3240.02 -455.01,3261.96 -455.01,3559.47 -398.06,3616.42 -126.08,3616.42 277.18,4019.68 1548.84,4019.68 1642.2,4113.05 1791.8,4113.05 1808.21,4129.46 1808.21,4147.2 1800.21,4155.2 v1(1800.21,4157.48) ; v1(2389.76,4203.59) 2392.05,4203.59 2400.05,4211.59 2430.68,4211.59 2436.02,4206.25 J14.25@2475.2,4206.25
  L6-BOT w3.3: v1(1800.21,4157.48) 1800.21,4155.2 1808.21,4147.2 1808.21,4138.21 1822.78,4123.63 1895.69,4123.63 1983.64,4211.59 2184.92,4211.59 2379.48,4211.59 2387.48,4203.59 v1(2389.76,4203.59)
PORTE_S0: J14.14 MC3.158 | length 4164.4
  L1-TOP w4.96: v1(-816.93,3690.95) MC3.158@-816.93,3736.61 ; v2(2178.19,4029.08) J14.14@2249.21,4029.08
  L6-BOT w4.96: v1(-816.93,3690.95) -816.93,3651.58 -657.48,3492.13 -280.49,3492.13 -257.64,3514.98 967.83,3514.98 1212.65,3759.79 1259,3806.15 cw(c1263.24,3801.91) 1267.48,3806.15 1305.66,3767.97 ccw(c1309.9,3772.2) 1314.13,3767.97 1326.85,3780.68 ccw(c1322.61,3784.92) 1326.85,3789.15 1284.86,3831.14 cw(c1289.1,3835.37) 1284.86,3839.61 1297.57,3852.32 cw(c1301.81,3848.09) 1306.05,3852.32 1354.51,3803.86 ccw(c1358.75,3808.1) 1362.99,3803.86 1375.7,3816.57 ccw(c1371.46,3820.81) 1375.7,3825.05 1327.24,3873.51 cw(c1331.47,3877.75) 1327.24,3881.99 1339.95,3894.7 cw(c1344.19,3890.46) 1348.42,3894.7 1396.89,3846.23 ccw(c1401.13,3850.47) 1405.36,3846.23 1418.08,3858.95 ccw(c1413.84,3863.18) 1418.07,3867.42 1369.61,3915.89 cw(c1373.85,3920.12) 1369.61,3924.36 1382.32,3937.07 cw(c1386.56,3932.84) 1390.8,3937.07 1439.26,3888.61 ccw(c1443.5,3892.84) 1447.74,3888.61 1460.45,3901.32 ccw(c1456.21,3905.56) 1460.45,3909.79 1411.98,3958.26 cw(c1416.22,3962.5) 1411.98,3966.73 1424.7,3979.45 cw(c1428.93,3975.21) 1433.17,3979.45 1481.64,3930.98 ccw(c1485.87,3935.22) 1490.11,3930.98 1502.82,3943.69 ccw(c1498.59,3947.93) 1502.82,3952.17 1458.16,3996.83 cw(c1462.4,4001.07) 1458.16,4005.31 1459.92,4007.06 1470.11,4017.26 2120.02,4017.26 2131.85,4029.08 v2(2178.19,4029.08)
PORTE_S1: J14.16 MC3.166 | length 4119.7
  L1-TOP w4.96: v1(-755.91,3661.42) -738.19,3679.13 MC3.166@-738.19,3736.61
  L6-BOT w4.96: v1(-755.91,3661.42) -610.24,3515.75 -280.86,3515.75 -264.66,3531.94 -211.22,3531.94 -176.24,3566.93 -110.24,3566.93 -77.79,3566.93 cw(c-77.79,3560.94) -71.8,3560.94 -71.8,3540.84 ccw(c-65.81,3540.84) -65.81,3534.85 -47.83,3534.85 ccw(c-47.83,3540.84) -41.84,3540.84 -41.84,3562.36 cw(c-35.84,3562.36) -35.84,3568.36 -17.87,3568.36 cw(c-17.87,3562.36) -11.87,3562.36 -11.87,3540.84 ccw(c-5.88,3540.84) -5.88,3534.85 12.1,3534.85 ccw(c12.1,3540.84) 18.09,3540.84 18.09,3562.36 cw(c24.08,3562.36) 24.08,3568.36 42.06,3568.36 cw(c42.06,3562.36) 48.05,3562.36 48.05,3540.84 ccw(c54.05,3540.84) 54.05,3534.85 72.02,3534.85 ccw(c72.02,3540.84) 78.02,3540.84 78.02,3562.36 cw(c84.01,3562.36) 84.01,3568.36 101.99,3568.36 cw(c101.99,3562.36) 107.98,3562.36 107.98,3540.84 ccw(c113.97,3540.84) 113.97,3534.85 131.95,3534.85 ccw(c131.95,3540.84) 137.94,3540.84 137.94,3562.36 cw(c143.93,3562.36) 143.93,3568.36 161.91,3568.36 cw(c161.91,3562.36) 167.91,3562.36 167.91,3540.84 ccw(c173.9,3540.84) 173.9,3534.85 191.88,3534.85 ccw(c191.88,3540.84) 197.87,3540.84 197.87,3562.36 cw(c203.86,3562.36) 203.86,3568.36 221.84,3568.36 cw(c221.84,3562.36) 227.83,3562.36 227.83,3540.84 ccw(c233.82,3540.84) 233.82,3534.85 251.8,3534.85 ccw(c251.8,3540.84) 257.79,3540.84 257.79,3560.94 cw(c263.79,3560.94) 263.79,3566.94 281.76,3566.94 cw(c281.76,3560.94) 287.76,3560.94 287.76,3540.84 ccw(c293.75,3540.84) 293.75,3534.85 311.73,3534.85 ccw(c311.73,3540.84) 317.72,3540.84 317.72,3560.94 cw(c323.71,3560.94) 323.71,3566.93 341.69,3566.93 cw(c341.69,3560.94) 347.68,3560.94 347.68,3540.84 ccw(c353.68,3540.84) 353.68,3534.85 371.65,3534.85 ccw(c371.65,3540.84) 377.65,3540.84 377.65,3560.94 cw(c383.64,3560.94) 383.64,3566.93 401.62,3566.93 cw(c401.62,3560.94) 407.61,3560.94 407.61,3540.84 ccw(c413.6,3540.84) 413.6,3534.85 431.58,3534.85 ccw(c431.58,3540.84) 437.57,3540.84 437.57,3560.94 cw(c443.57,3560.94) 443.57,3566.93 461.54,3566.93 cw(c461.54,3560.94) 467.54,3560.94 467.54,3540.84 ccw(c473.53,3540.84) 473.53,3534.85 491.51,3534.85 ccw(c491.51,3540.84) 497.5,3540.84 497.5,3560.94 cw(c503.49,3560.94) 503.49,3566.93 521.47,3566.93 cw(c521.47,3560.94) 527.46,3560.94 527.46,3540.84 ccw(c533.45,3540.84) 533.45,3534.85 551.43,3534.85 ccw(c551.43,3540.84) 557.42,3540.84 557.42,3560.94 cw(c563.42,3560.94) 563.42,3566.93 581.39,3566.93 cw(c581.39,3560.94) 587.39,3560.94 587.39,3540.84 ccw(c593.38,3540.84) 593.38,3534.85 611.36,3534.85 ccw(c611.36,3540.84) 617.35,3540.84 617.35,3560.94 cw(c623.34,3560.94) 623.34,3566.93 641.32,3566.93 cw(c641.32,3560.94) 647.31,3560.94 647.31,3540.84 ccw(c653.31,3540.84) 653.31,3534.85 671.28,3534.85 ccw(c671.28,3540.84) 677.28,3540.84 677.28,3560.94 cw(c683.27,3560.94) 683.27,3566.93 701.25,3566.93 cw(c701.25,3560.94) 707.24,3560.94 707.24,3540.84 ccw(c713.23,3540.84) 713.23,3534.85 731.21,3534.85 ccw(c731.21,3540.84) 737.2,3540.84 737.2,3560.94 cw(c743.19,3560.94) 743.19,3566.93 761.17,3566.93 cw(c761.17,3560.94) 767.17,3560.94 767.17,3554.6 ccw(c773.16,3554.6) 773.16,3548.6 791.14,3548.6 ccw(c791.14,3554.6) 797.13,3554.6 797.13,3560.94 cw(c803.12,3560.94) 803.12,3566.93 885.83,3566.93 988.19,3566.93 1455.48,4034.22 2113,4034.22 2128.95,4050.18 v2(2204.53,4050.18)
PORTE_S2: J14.17 MC3.164 | length 4119.6
  L1-TOP w4.96: MC3.164@-757.87,3736.61 -757.87,3781.5 -740.16,3799.21 v1(-712.6,3799.21)
  L6-BOT w4.96: v1(-712.6,3799.21) -688.98,3775.59 -637.18,3775.59 -562.99,3849.78 -562.99,3948.86 -529.61,3982.24 -503.36,3982.24 -486.86,3982.24 -355.87,4113.23 -97.85,4113.23 -43.67,4059.06 1136.51,4059.06 1573.52,4496.06 1929.25,4496.06 2311.02,4496.06 2334.65,4519.68 2377.88,4519.68 2401.57,4495.99 2401.57,4417.32 2417.32,4401.57 2449.59,4401.57 2493.9,4357.27 2493.9,4112.71 v2(2519.88,4086.73)
PORTE_S3: J14.18 MC3.170 | length 4119.7
  L1-TOP w4.96: MC3.170@-698.82,3736.61 -698.82,3698.45 -688.98,3688.61 v1(-688.98,3649.61)
  L6-BOT w4.96: v1(-688.98,3649.61) -688.98,3645.67 -638.04,3594.73 -122.44,3594.73 -99.06,3618.11 -82.68,3618.11 216.77,3618.11 cw(c216.77,3612.12) 222.77,3612.12 222.77,3602.53 ccw(c228.76,3602.53) 228.76,3596.54 246.74,3596.54 ccw(c246.74,3602.53) 252.73,3602.53 252.73,3615.64 cw(c258.72,3615.64) 258.72,3621.63 276.7,3621.63 cw(c276.7,3615.64) 282.69,3615.64 282.69,3589.88 ccw(c288.68,3589.88) 288.68,3583.89 306.66,3583.89 ccw(c306.66,3589.88) 312.65,3589.88 312.65,3615.64 cw(c318.65,3615.64) 318.65,3621.63 336.62,3621.63 cw(c336.62,3615.64) 342.62,3615.64 342.62,3589.88 ccw(c348.61,3589.88) 348.61,3583.89 366.59,3583.89 ccw(c366.59,3589.88) 372.58,3589.88 372.58,3615.64 cw(c378.57,3615.64) 378.57,3621.63 396.55,3621.63 cw(c396.55,3615.64) 402.54,3615.64 402.54,3589.88 ccw(c408.54,3589.88) 408.54,3583.89 426.51,3583.89 ccw(c426.51,3589.88) 432.51,3589.88 432.51,3615.64 cw(c438.5,3615.64) 438.5,3621.63 456.48,3621.63 cw(c456.48,3615.64) 462.47,3615.64 462.47,3589.88 ccw(c468.46,3589.88) 468.46,3583.89 486.44,3583.89 ccw(c486.44,3589.88) 492.43,3589.88 492.43,3615.64 cw(c498.42,3615.64) 498.42,3621.63 516.4,3621.63 cw(c516.4,3615.64) 522.4,3615.64 522.4,3589.88 ccw(c528.39,3589.88) 528.39,3583.89 546.37,3583.89 ccw(c546.37,3589.88) 552.36,3589.88 552.36,3615.64 cw(c558.35,3615.64) 558.35,3621.63 576.33,3621.63 cw(c576.33,3615.64) 582.32,3615.64 582.32,3589.88 ccw(c588.31,3589.88) 588.31,3583.89 606.29,3583.89 ccw(c606.29,3589.88) 612.28,3589.88 612.28,3615.64 cw(c618.28,3615.64) 618.28,3621.63 636.25,3621.63 cw(c636.25,3615.64) 642.25,3615.64 642.25,3589.88 ccw(c648.24,3589.88) 648.24,3583.89 666.22,3583.89 ccw(c666.22,3589.88) 672.21,3589.88 672.21,3615.64 cw(c678.2,3615.64) 678.2,3621.63 696.18,3621.63 cw(c696.18,3615.64) 702.17,3615.64 702.17,3589.88 ccw(c708.17,3589.88) 708.17,3583.89 726.14,3583.89 ccw(c726.14,3589.88) 732.14,3589.88 732.14,3615.64 cw(c738.13,3615.64) 738.13,3621.63 756.11,3621.63 cw(c756.11,3615.64) 762.1,3615.64 762.1,3589.88 ccw(c768.09,3589.88) 768.09,3583.89 786.07,3583.89 ccw(c786.07,3589.88) 792.06,3589.88 792.06,3615.64 cw(c798.06,3615.64) 798.06,3621.63 816.03,3621.63 cw(c816.03,3615.64) 822.03,3615.64 822.03,3589.88 ccw(c828.02,3589.88) 828.02,3583.89 846,3583.89 ccw(c846,3589.88) 851.99,3589.88 851.99,3615.64 cw(c857.98,3615.64) 857.98,3621.63 875.96,3621.63 cw(c875.96,3615.64) 881.95,3615.64 881.95,3589.88 ccw(c887.94,3589.88) 887.94,3583.89 905.92,3583.89 ccw(c905.92,3589.88) 911.91,3589.88 911.91,3615.64 cw(c917.91,3615.64) 917.91,3621.63 935.88,3621.63 cw(c935.88,3615.64) 941.88,3615.64 941.88,3589.88 ccw(c947.87,3589.88) 947.87,3583.89 965.85,3583.89 ccw(c965.85,3589.88) 971.84,3589.88 971.84,3612.12 cw(c977.83,3612.12) 977.83,3618.11 980.32,3618.11 1011.81,3618.11 1444.88,4051.18 1970.98,4051.18 2008.6,4088.8 2291.83,4088.8 v2(2293.9,4086.73)
PORTE_S4: J14.19 MC3.176 | length 4119.7
  L1-TOP w4.96: MC3.176@-639.76,3736.61 -639.76,3698.82 -622.05,3681.1 -559.06,3681.1 v1(-527.56,3712.6)
  L6-BOT w4.96: v1(-527.56,3712.6) -527.56,3787.4 -541.05,3800.89 -541.05,3868.56 -503.36,3906.25 -485.37,3924.24 -485.37,3959.74 -348.85,4096.26 -104.87,4096.26 -8.61,4000 11.81,4000 14.29,4000 ccw(c14.29,4005.99) 20.29,4005.99 20.29,4019.01 cw(c26.28,4019.01) 26.28,4025 44.26,4025 cw(c44.26,4019.01) 50.25,4019.01 50.25,3984.03 ccw(c56.24,3984.03) 56.24,3978.04 74.22,3978.04 ccw(c74.22,3984.03) 80.21,3984.03 80.21,3994.01 cw(c86.2,3994.01) 86.2,4000 133.86,4000 1112.21,4000 1584.65,4472.44 2326.77,4472.44 2338.58,4460.63 2338.58,4397.64 2354.33,4381.89 2433.07,4381.89 2476.91,4338.05 2476.91,4155.63 v2(2430.51,4109.23)
PORTE_S5: J14.20 MC3.172 | length 4119.7
  L1-TOP w4.96: MC3.172@-679.13,3736.61 -679.13,3702.76 v1(-625.98,3649.61)
  L6-BOT w4.96: v1(-625.98,3649.61) -593.31,3616.93 -124.23,3616.93 -67.93,3673.23 -59.06,3673.23 -26.61,3673.23 cw(c-26.61,3667.24) -20.62,3667.24 -20.62,3644.55 ccw(c-14.62,3644.55) -14.62,3638.56 3.35,3638.56 ccw(c3.35,3644.55) 9.35,3644.55 9.35,3669.3 cw(c15.34,3669.3) 15.34,3675.29 33.32,3675.29 cw(c33.32,3669.3) 39.31,3669.3 39.31,3644.55 ccw(c45.3,3644.55) 45.3,3638.56 63.28,3638.56 ccw(c63.28,3644.55) 69.27,3644.55 69.27,3669.3 cw(c75.26,3669.3) 75.26,3675.29 93.24,3675.29 cw(c93.24,3669.3) 99.23,3669.3 99.23,3644.55 ccw(c105.23,3644.55) 105.23,3638.56 123.2,3638.56 ccw(c123.2,3644.55) 129.2,3644.55 129.2,3669.3 cw(c135.19,3669.3) 135.19,3675.29 153.17,3675.29 cw(c153.17,3669.3) 159.16,3669.3 159.16,3644.55 ccw(c165.15,3644.55) 165.15,3638.56 183.13,3638.56 ccw(c183.13,3644.55) 189.12,3644.55 189.12,3669.3 cw(c195.12,3669.3) 195.12,3675.29 213.09,3675.29 cw(c213.09,3669.3) 219.09,3669.3 219.09,3644.55 ccw(c225.08,3644.55) 225.08,3638.56 243.06,3638.56 ccw(c243.06,3644.55) 249.05,3644.55 249.05,3669.3 cw(c255.04,3669.3) 255.04,3675.29 273.02,3675.29 cw(c273.02,3669.3) 279.01,3669.3 279.01,3644.55 ccw(c285.01,3644.55) 285.01,3638.56 302.98,3638.56 ccw(c302.98,3644.55) 308.98,3644.55 308.98,3669.3 cw(c314.97,3669.3) 314.97,3675.29 332.95,3675.29 cw(c332.95,3669.3) 338.94,3669.3 338.94,3644.55 ccw(c344.93,3644.55) 344.93,3638.56 362.91,3638.56 ccw(c362.91,3644.55) 368.9,3644.55 368.9,3669.3 cw(c374.89,3669.3) 374.89,3675.29 392.87,3675.29 cw(c392.87,3669.3) 398.86,3669.3 398.86,3644.55 ccw(c404.86,3644.55) 404.86,3638.56 422.83,3638.56 ccw(c422.83,3644.55) 428.83,3644.55 428.83,3669.3 cw(c434.82,3669.3) 434.82,3675.29 452.8,3675.29 cw(c452.8,3669.3) 458.79,3669.3 458.79,3644.55 ccw(c464.78,3644.55) 464.78,3638.56 482.76,3638.56 ccw(c482.76,3644.55) 488.75,3644.55 488.75,3669.3 cw(c494.75,3669.3) 494.75,3675.29 512.72,3675.29 cw(c512.72,3669.3) 518.72,3669.3 518.72,3644.55 ccw(c524.71,3644.55) 524.71,3638.56 542.69,3638.56 ccw(c542.69,3644.55) 548.68,3644.55 548.68,3669.3 cw(c554.67,3669.3) 554.67,3675.29 572.65,3675.29 cw(c572.65,3669.3) 578.64,3669.3 578.64,3644.55 ccw(c584.64,3644.55) 584.64,3638.56 602.61,3638.56 ccw(c602.61,3644.55) 608.61,3644.55 608.61,3669.3 cw(c614.6,3669.3) 614.6,3675.29 632.58,3675.29 cw(c632.58,3669.3) 638.57,3669.3 638.57,3644.55 ccw(c644.56,3644.55) 644.56,3638.56 662.54,3638.56 ccw(c662.54,3644.55) 668.53,3644.55 668.53,3669.3 cw(c674.52,3669.3) 674.52,3675.29 692.5,3675.29 cw(c692.5,3669.3) 698.49,3669.3 698.49,3644.55 ccw(c704.49,3644.55) 704.49,3638.56 722.46,3638.56 ccw(c722.46,3644.55) 728.46,3644.55 728.46,3669.3 cw(c734.45,3669.3) 734.45,3675.29 752.43,3675.29 cw(c752.43,3669.3) 758.42,3669.3 758.42,3644.55 ccw(c764.41,3644.55) 764.41,3638.56 782.39,3638.56 ccw(c782.39,3644.55) 788.38,3644.55 788.38,3669.3 cw(c794.38,3669.3) 794.38,3675.29 812.35,3675.29 cw(c812.35,3669.3) 818.35,3669.3 818.35,3644.55 ccw(c824.34,3644.55) 824.34,3638.56 842.32,3638.56 ccw(c842.32,3644.55) 848.31,3644.55 848.31,3669.3 cw(c854.3,3669.3) 854.3,3675.29 872.28,3675.29 cw(c872.28,3669.3) 878.27,3669.3 878.27,3666.5 ccw(c884.27,3666.5) 884.27,3660.51 902.24,3660.51 ccw(c902.24,3666.5) 908.24,3666.5 908.24,3667.24 cw(c914.23,3667.24) 914.23,3673.23 973.7,3673.23 1031.5,3673.23 1426.41,4068.14 1963.11,4068.14 2004.2,4109.23 v2(2204.53,4109.23)
PORTE_S6: J14.21 MC3.160 | length 4119.7
  L1-TOP w4.96: MC3.160@-797.24,3736.61 -797.24,3777.56 -748.03,3826.77 v1(-661.42,3826.77)
  L6-BOT w4.96: v1(-661.42,3826.77) -585.19,3903 -585.19,3952.79 -537.03,4000.95 -503.36,4000.95 -492.14,4000.95 -468.99,4024.1 -467.23,4025.86 ccw(c-471.47,4030.1) -467.23,4034.33 -467.66,4034.76 cw(c-463.42,4039) -467.66,4043.23 -454.94,4055.94 cw(c-450.71,4051.71) -446.47,4055.94 -446.04,4055.52 ccw(c-441.81,4059.76) -437.57,4055.52 -413.87,4079.22 -362.9,4130.19 -90.82,4130.19 -43.31,4082.68 1118.33,4082.68 1553.91,4518.26 1920.05,4518.26 1976.98,4575.19 2380.57,4575.19 2511.81,4443.95 2511.81,4155.4 2519.88,4147.33 v2(2519.88,4145.79)
PORTE_S7: J14.22 MC3.168 | length 4119.7
  L1-TOP w4.96: v1(-718.5,3690.95) MC3.168@-718.5,3736.61
  L6-BOT w4.96: v1(-718.5,3690.95) -716.54,3692.91 -586.61,3692.91 -532.83,3639.13 -126.02,3639.13 -28.93,3736.22 282.49,3736.22 314.93,3736.22 cw(c314.93,3730.23) 320.92,3730.23 320.92,3703.24 ccw(c326.92,3703.24) 326.92,3697.25 344.89,3697.25 ccw(c344.89,3703.24) 350.89,3703.24 350.89,3731.42 cw(c356.88,3731.42) 356.88,3737.41 374.86,3737.41 cw(c374.86,3731.42) 380.85,3731.42 380.85,3703.24 ccw(c386.84,3703.24) 386.84,3697.25 404.82,3697.25 ccw(c404.82,3703.24) 410.81,3703.24 410.81,3731.42 cw(c416.81,3731.42) 416.81,3737.41 434.78,3737.41 cw(c434.78,3731.42) 440.78,3731.42 440.78,3703.24 ccw(c446.77,3703.24) 446.77,3697.25 464.75,3697.25 ccw(c464.75,3703.24) 470.74,3703.24 470.74,3731.42 cw(c476.73,3731.42) 476.73,3737.41 494.71,3737.41 cw(c494.71,3731.42) 500.7,3731.42 500.7,3703.24 ccw(c506.69,3703.24) 506.69,3697.25 524.67,3697.25 ccw(c524.67,3703.24) 530.67,3703.24 530.67,3731.42 cw(c536.66,3731.42) 536.66,3737.41 554.64,3737.41 cw(c554.64,3731.42) 560.63,3731.42 560.63,3703.24 ccw(c566.62,3703.24) 566.62,3697.25 584.6,3697.25 ccw(c584.6,3703.24) 590.59,3703.24 590.59,3731.42 cw(c596.58,3731.42) 596.58,3737.41 614.56,3737.41 cw(c614.56,3731.42) 620.55,3731.42 620.55,3703.24 ccw(c626.55,3703.24) 626.55,3697.25 644.52,3697.25 ccw(c644.52,3703.24) 650.52,3703.24 650.52,3731.42 cw(c656.51,3731.42) 656.51,3737.41 674.49,3737.41 cw(c674.49,3731.42) 680.48,3731.42 680.48,3703.24 ccw(c686.47,3703.24) 686.47,3697.25 704.45,3697.25 ccw(c704.45,3703.24) 710.44,3703.24 710.44,3731.42 cw(c716.44,3731.42) 716.44,3737.41 734.41,3737.41 cw(c734.41,3731.42) 740.41,3731.42 740.41,3703.24 ccw(c746.4,3703.24) 746.4,3697.25 764.38,3697.25 ccw(c764.38,3703.24) 770.37,3703.24 770.37,3731.42 cw(c776.36,3731.42) 776.36,3737.41 794.34,3737.41 cw(c794.34,3731.42) 800.33,3731.42 800.33,3703.24 ccw(c806.32,3703.24) 806.32,3697.25 824.3,3697.25 ccw(c824.3,3703.24) 830.3,3703.24 830.3,3731.42 cw(c836.29,3731.42) 836.29,3737.41 854.27,3737.41 cw(c854.27,3731.42) 860.26,3731.42 860.26,3703.24 ccw(c866.25,3703.24) 866.25,3697.25 884.23,3697.25 ccw(c884.23,3703.24) 890.22,3703.24 890.22,3731.42 cw(c896.21,3731.42) 896.21,3737.41 914.19,3737.41 cw(c914.19,3731.42) 920.18,3731.42 920.18,3703.24 ccw(c926.18,3703.24) 926.18,3697.25 944.15,3697.25 ccw(c944.15,3703.24) 950.15,3703.24 950.15,3731.42 cw(c956.14,3731.42) 956.14,3737.41 974.12,3737.41 cw(c974.12,3731.42) 980.11,3731.42 980.11,3711.19 ccw(c986.1,3711.19) 986.1,3705.2 1004.08,3705.2 ccw(c1004.08,3711.19) 1010.07,3711.19 1010.07,3730.23 cw(c1016.07,3730.23) 1016.07,3736.22 1043.31,3736.22 1062.99,3736.22 1411.88,4085.11 1955.5,4085.11 2009.78,4139.38 2151.19,4139.38 2165.35,4153.54 2190.62,4153.54 2198.38,4145.79 v2(2293.9,4145.79)
PORTE_S8: J14.23 MC3.174 | length 4119.7
  L1-TOP w4.96: MC3.174@-659.45,3736.61 -659.45,3781.5 -609.85,3831.09 -503.36,3831.09 -493.28,3831.09 -482.12,3842.25 v1(-482.12,3857.44)
  L6-BOT w4.96: v1(-482.12,3857.44) -482.12,3888.57 -465.45,3905.25 -465.45,3955.68 -341.82,4079.3 -111.9,4079.3 34.33,3933.07 826.77,3933.07 829.25,3933.07 ccw(c829.25,3939.06) 835.25,3939.06 835.25,3952.08 cw(c841.24,3952.08) 841.24,3958.07 859.22,3958.07 cw(c859.22,3952.08) 865.21,3952.08 865.21,3914.06 ccw(c871.2,3914.06) 871.2,3908.07 889.18,3908.07 ccw(c889.18,3914.06) 895.17,3914.06 895.17,3952.08 cw(c901.16,3952.08) 901.16,3958.07 919.14,3958.07 cw(c919.14,3952.08) 925.14,3952.08 925.14,3914.06 ccw(c931.13,3914.06) 931.13,3908.07 949.11,3908.07 ccw(c949.11,3914.06) 955.1,3914.06 955.1,3952.08 cw(c961.09,3952.08) 961.09,3958.07 979.07,3958.07 cw(c979.07,3952.08) 985.06,3952.08 985.06,3920.42 ccw(c991.05,3920.42) 991.05,3914.42 1009.03,3914.42 ccw(c1009.03,3920.42) 1015.02,3920.42 1015.02,3927.08 cw(c1021.02,3927.08) 1021.02,3933.07 1066.93,3933.07 1085.76,3933.07 1601.51,4448.82 2184.92,4448.82 2303.15,4448.82 2318.9,4433.07 2318.9,4377.95 2342.52,4354.33 2425.2,4354.33 2460.63,4318.9 2460.63,4198.41 v2(2430.51,4168.29)
PORTE_S9: J14.24 MC3.162 | length 4119.7
  L1-TOP w4.96: v1(-777.56,3690.95) MC3.162@-777.56,3736.61
  L6-BOT w4.96: v1(-777.56,3690.95) -751.97,3716.54 -582.68,3716.54 -527.56,3661.42 -133.86,3661.42 3.94,3799.21 23.62,3799.21 56.07,3799.21 cw(c56.07,3793.22) 62.06,3793.22 62.06,3764.29 ccw(c68.05,3764.29) 68.05,3758.29 86.03,3758.29 ccw(c86.03,3764.29) 92.02,3764.29 92.02,3803.97 cw(c98.02,3803.97) 98.02,3809.96 115.99,3809.96 cw(c115.99,3803.97) 121.99,3803.97 121.99,3764.29 ccw(c127.98,3764.29) 127.98,3758.29 145.96,3758.29 ccw(c145.96,3764.29) 151.95,3764.29 151.95,3803.97 cw(c157.94,3803.97) 157.94,3809.96 175.92,3809.96 cw(c175.92,3803.97) 181.91,3803.97 181.91,3764.29 ccw(c187.9,3764.29) 187.9,3758.29 205.88,3758.29 ccw(c205.88,3764.29) 211.87,3764.29 211.87,3803.97 cw(c217.87,3803.97) 217.87,3809.96 235.84,3809.96 cw(c235.84,3803.97) 241.84,3803.97 241.84,3764.29 ccw(c247.83,3764.29) 247.83,3758.29 265.81,3758.29 ccw(c265.81,3764.29) 271.8,3764.29 271.8,3803.97 cw(c277.79,3803.97) 277.79,3809.96 295.77,3809.96 cw(c295.77,3803.97) 301.76,3803.97 301.76,3764.29 ccw(c307.76,3764.29) 307.76,3758.29 325.73,3758.29 ccw(c325.73,3764.29) 331.73,3764.29 331.73,3803.97 cw(c337.72,3803.97) 337.72,3809.96 355.7,3809.96 cw(c355.7,3803.97) 361.69,3803.97 361.69,3764.29 ccw(c367.68,3764.29) 367.68,3758.29 385.66,3758.29 ccw(c385.66,3764.29) 391.65,3764.29 391.65,3803.97 cw(c397.65,3803.97) 397.65,3809.96 415.62,3809.96 cw(c415.62,3803.97) 421.62,3803.97 421.62,3764.29 ccw(c427.61,3764.29) 427.61,3758.29 445.59,3758.29 ccw(c445.59,3764.29) 451.58,3764.29 451.58,3803.97 cw(c457.57,3803.97) 457.57,3809.96 475.55,3809.96 cw(c475.55,3803.97) 481.54,3803.97 481.54,3764.29 ccw(c487.53,3764.29) 487.53,3758.29 505.51,3758.29 ccw(c505.51,3764.29) 511.5,3764.29 511.5,3803.97 cw(c517.5,3803.97) 517.5,3809.96 535.48,3809.96 cw(c535.48,3803.97) 541.47,3803.97 541.47,3764.29 ccw(c547.46,3764.29) 547.46,3758.29 565.44,3758.29 ccw(c565.44,3764.29) 571.43,3764.29 571.43,3802.7 cw(c577.42,3802.7) 577.42,3808.7 595.4,3808.7 cw(c595.4,3802.7) 601.39,3802.7 601.39,3793.22 ccw(c607.39,3793.22) 607.39,3787.23 625.36,3787.23 ccw(c625.36,3793.22) 631.36,3793.22 cw(c637.35,3793.22) 637.35,3799.21 724.41,3799.21 1086.61,3799.21 1389.47,4102.07 1948.47,4102.07 2013.43,4167.03 2203.27,4167.03 v2(2204.53,4168.29)
PORTE_TX0_N: J14.8 MC2.116 | length 2582.4
  L1-TOP w3.3: MC2.116@-114.57,3395.67 -91.93,3395.67 -86.59,3390.33 -66.84,3390.33 -61.42,3390.33 -41.15,3390.33 421.73,3853.21 1640.19,3853.21 1664.19,3877.21 1677.56,3890.58 1677.56,3901.89 v1(1679.17,3903.5)
  L6-BOT w3.3: v1(1679.17,3903.5) 1680.79,3905.12 1692.1,3905.12 1699.53,3912.55 1741.43,3912.55 1777.15,3876.83 2083.14,3876.83 2131.63,3925.32 2184.92,3925.32 2194.24,3925.32 2202.24,3933.32 v1(2204.53,3933.32)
